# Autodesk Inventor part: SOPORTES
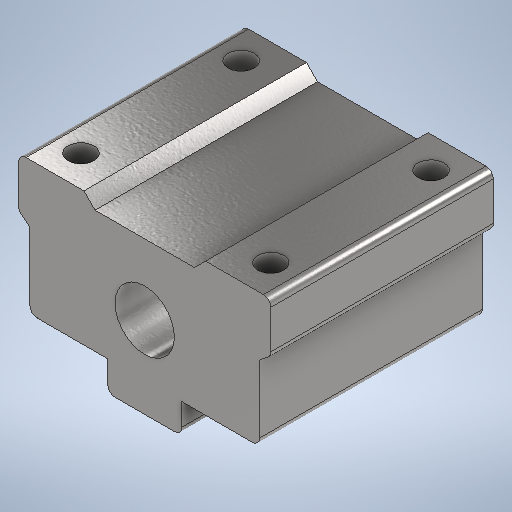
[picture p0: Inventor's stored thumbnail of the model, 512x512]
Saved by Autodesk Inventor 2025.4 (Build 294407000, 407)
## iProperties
Created: 2026-04
Part Number: SOPORTES
Material: Steel, Galvanized
Document SubType Name: Modeling
Designer: PC
Density: 7.85 g/cm^3
Appearance: Galvanized
Author: PC
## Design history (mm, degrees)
sketch "Sketch1"
  geometry: L1 (17, -11)-(-17, -11); L2 (-17, -11)-(-17, 11); L3 (-17, 11)-(17, 11); L4 (17, 11)-(17, -11); L5 (17, -11)-(-17, 11); L6 (-17, -11)-(17, 11); L7 (0, -11)-(-5, -11); L8 (-5, -11)-(-5, -7); L9 (-5, -7)-(-17, -7); L10 (-5, -7)-(-8.4, -7); L11 (-8.4, -7)-(-5, -11); L12 (-17, 3.118)-(-15.5, 3.118); L13 (-15.5, 3.118)-(-15.5, -7); L14 (-6.7, 11)-(-6.7, 9.5); L15 (-6.7, 9.5)-(0, 9.5); L16 (0, 9.5)-(0, 11); L17 (-6.7, 11)-(-5.729, 9.5); L18 (-17, 4.335)-(-15.5, 3.118); L19 (0, -11)-(5, -11); L20 (17, 3.118)-(15.5, 3.118); L21 (17, 4.335)-(15.5, 3.118); L22 (6.7, 9.5)-(0, 9.5); L23 (6.7, 11)-(6.7, 9.5); L24 (6.7, 11)-(5.729, 9.5); L25 (17, -11)-(17, 11); L26 (5, -11)-(5, -7); L27 (8.4, -7)-(5, -11); L28 (5, -7)-(17, -7); L29 (15.5, 3.118)-(15.5, -7); L30 (5, -7)-(8.4, -7); C1 r 4 at (0, 0); C2 r 5 at (0, 0); C3 r 5 at (0, 0); C4 r 4 at (0, 0); 4 further points
  constraints: 60 end point, 16 point on line, 11 symmetric about line, 6 perpendicular, 4 centre point, 4 coincident, 4 midpoint, 2 parallel, 1 horizontal, 1 vertical, 2 other
  dimensions: "d0" = 34 distance of L2.end L3.end; "d1" = 22 distance of L1.end L2.end; "d2" = 5 distance of L7.start L7.end; "d3" = 4 distance of L7.end L8.end; "d4" = 3.4 distance of L8.end L10.end; "d5" = 1.5 distance of L12.start L12.end; "d6" = 1.5 distance of L14.start L14.end; "d7" = 8 diameter of C1; "d8" = 10 diameter of C2
extrude "Extrusion1" new body sketch "Sketch1" distance "d9" = 30; taper "d10" = 0 deg
extrude "Extrusion2" cut sketch "Sketch1" distance "d11" = 1; taper "d12" = 0 deg
sketch "Sketch2"
  geometry: L1 (-13.4, -30)-(-23.7, -30) reference; L2 (-23.7, 0)-(-23.7, -30) reference; L3 (-13.4, 0)-(-23.7, 0) reference; L4 (10.3, 0)-(10.3, -30) reference; L5 (10.3, 0)-(0, 0) reference; L6 (10.3, -30)-(0, -30) reference; C1 r 1.75 at (6.1, -25.8); C2 r 1.75 at (6.1, -4.2); C3 r 1.75 at (-19.5, -25.8); C4 r 1.75 at (-19.5, -4.2); 3 further points
  constraints: 4 centre point, 2 midpoint
  dimensions: "d13" = 3.5 diameter of C1; "d14" = 3.5 diameter of C2; "d15" = 3.5 diameter of C3; "d16" = 3.5 diameter of C4; "d17" = 4.2 vertical distance of point (-18.55, -30) C3.centre; "d18" = 4.2 distance from line of L2 C3.centre; "d19" = 4.2 distance from line of L3 C4.centre; "d20" = 4.2 distance from line of L2 C4.centre; "d21" = 4.2 distance from line of L4 C2.centre; "d22" = 4.2 vertical distance of point (5.15, 0) C2.centre; "d23" = 4.2 distance from line of L6 C1.centre; "d24" = 4.2 distance from line of L4 C1.centre
extrude "Extrusion3" cut sketch "Sketch2" extent not by distance; stored distance "d25" = 0; taper "d26" = 0 deg
fillet "Fillet1" dims "d27" = 1
fillet "Fillet2" dims "d28" = 1
chamfer "Chamfer1" distance "d29" = 1.5; stored, may be unused: second distance "d30" = 2, angle "d31" = 45 deg
body "Solid1"
